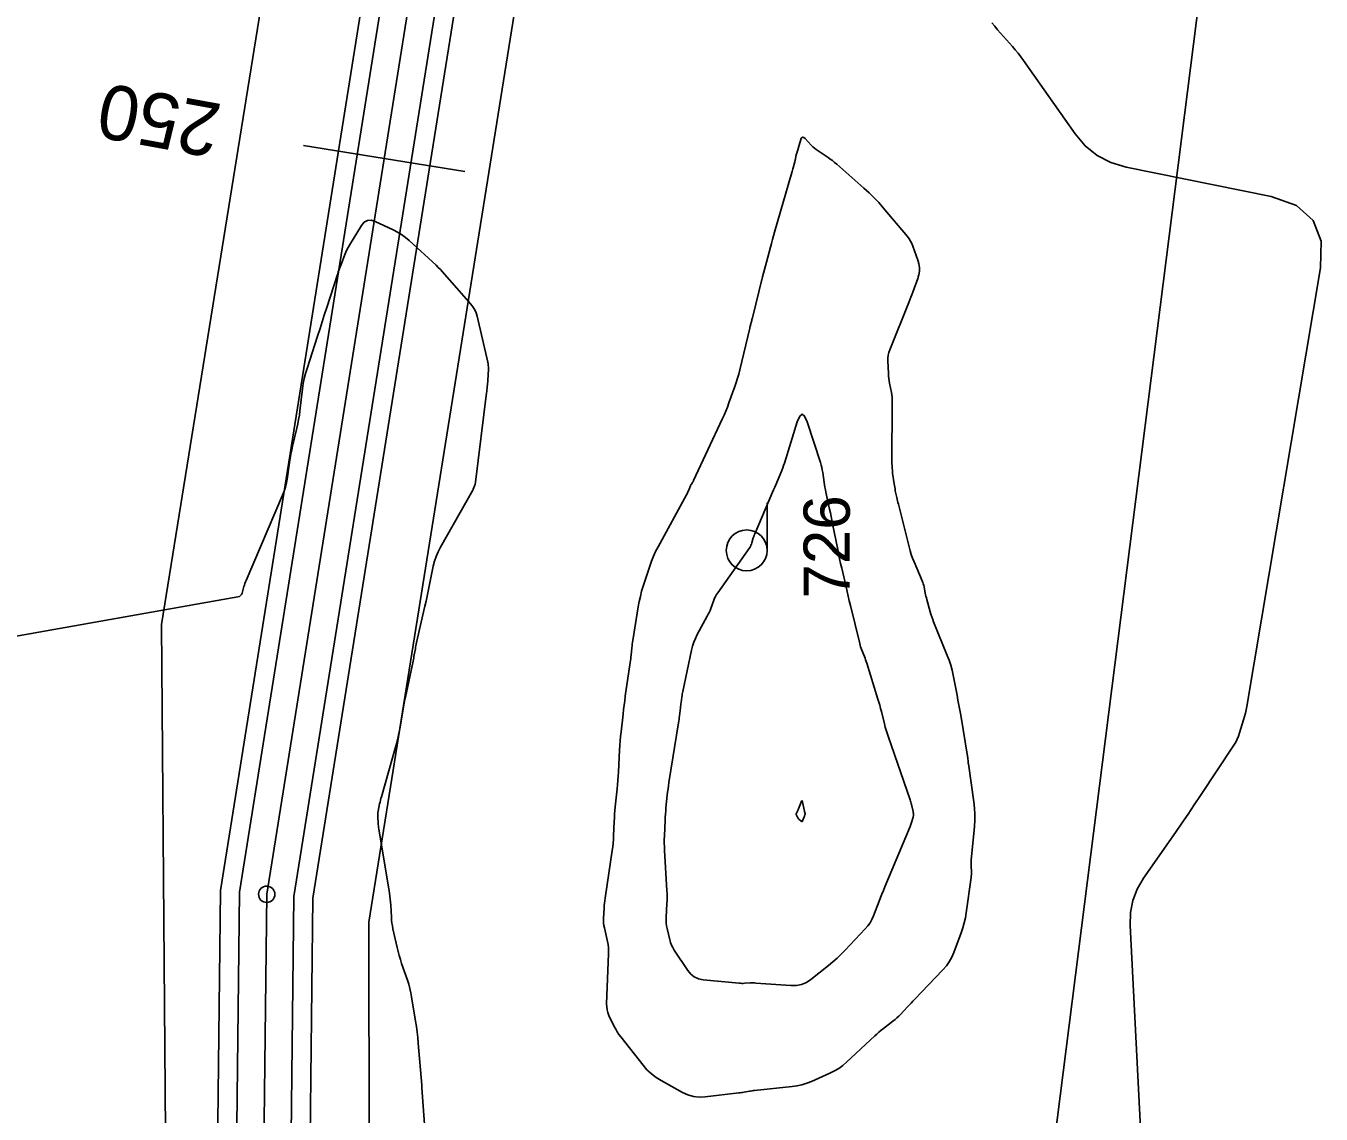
# Model space of a CAD drawing. Extents: x -534481 to -534262, y -1190577 to -1190138.
# Drawn here: x -534356 to -534332.21, y -1190332.35 to -1190312.37 of the extents above; entities that cross this region are included whole.
import ezdxf

# ---------------------------------------------------------------- set-up
doc = ezdxf.new("R2010")
doc.units = 0
for name, color, linetype in [('Bonity', 7, 'Continuous'), ('Definiční body', 7, 'Continuous'), ('Polygon budovy', 7, 'Continuous'), ('Vrstva 18', 7, 'Continuous'), ('Vrstva 19', 7, 'Continuous'), ('Vrstva 31', 7, 'Continuous'), ('Vrstva 32', 7, 'Continuous'), ('Vrstva 37', 7, 'Continuous'), ('Vrstva 48', 7, 'Continuous')]:
    doc.layers.add(name, color=color, linetype=linetype)

msp = doc.modelspace()

# ---------------------------------------------------------------- linework, layer by layer
at = {"layer": 'Bonity'}
msp.add_lwpolyline([(-534409.868, -1190391.439), (-534405.947, -1190382.816), (-534400.873, -1190377.487), (-534393.696, -1190372.718), (-534384.927, -1190365.477), (-534382.631, -1190361.148), (-534355.894, -1190347.823), (-534351.738, -1190342.389), (-534351.577, -1190328.316), (-534347.204, -1190300.921), (-534345.553, -1190283.64), (-534344.682, -1190264.494)], dxfattribs=at)
at = {"layer": 'Definiční body'}
msp.add_line((-534333.95, -1190307.91), (-534337.65, -1190337.15), dxfattribs=at)
for points in [[(-534353.4, -1190337.34), (-534353.51, -1190323.36), (-534348.1, -1190289.81), (-534348.02, -1190285.43)], [(-534346.16, -1190306.72), (-534349.7, -1190328.83), (-534349.69, -1190337.24)]]:
    msp.add_lwpolyline(points, dxfattribs=at)
at = {"layer": 'Vrstva 18'}
msp.add_lwpolyline([(-534334.528, -1190352.171), (-534335.719, -1190328.886), (-534335.712, -1190328.653), (-534335.669, -1190328.431), (-534335.588, -1190328.219), (-534335.471, -1190328.018), (-534334.888, -1190327.182), (-534334.771, -1190327.013), (-534334.655, -1190326.843), (-534334.54, -1190326.673), (-534334.426, -1190326.502), (-534333.813, -1190325.578), (-534333.78, -1190325.525), (-534333.751, -1190325.469), (-534333.727, -1190325.412), (-534333.707, -1190325.352), (-534333.634, -1190325.111), (-534333.616, -1190325.05), (-534333.601, -1190324.989), (-534333.588, -1190324.928), (-534333.576, -1190324.866), (-534332.224, -1190316.817), (-534332.211, -1190316.326), (-534332.357, -1190315.943), (-534332.662, -1190315.669), (-534333.126, -1190315.505), (-534335.793, -1190314.964), (-534336.073, -1190314.881), (-534336.322, -1190314.751), (-534336.542, -1190314.575), (-534336.73, -1190314.352), (-534337.677, -1190313.007), (-534337.725, -1190312.941), (-534337.775, -1190312.876), (-534337.827, -1190312.812), (-534337.88, -1190312.75), (-534338.098, -1190312.504), (-534338.152, -1190312.442), (-534338.205, -1190312.379), (-534338.257, -1190312.315)], dxfattribs=at)
msp.add_lwpolyline([(-534341.665, -1190329.934), (-534341.754, -1190329.972), (-534341.849, -1190329.991), (-534341.95, -1190329.993), (-534342.595, -1190329.945), (-534342.62, -1190329.944), (-534342.646, -1190329.943), (-534342.672, -1190329.943), (-534342.697, -1190329.944), (-534342.8, -1190329.95), (-534342.825, -1190329.951), (-534342.851, -1190329.951), (-534342.877, -1190329.95), (-534342.902, -1190329.948), (-534343.56, -1190329.884), (-534343.646, -1190329.867), (-534343.723, -1190329.832), (-534343.789, -1190329.781), (-534343.845, -1190329.713), (-534344.093, -1190329.339), (-534344.119, -1190329.295), (-534344.142, -1190329.248), (-534344.16, -1190329.2), (-534344.174, -1190329.15), (-534344.221, -1190328.946), (-534344.231, -1190328.895), (-534344.237, -1190328.844), (-534344.24, -1190328.792), (-534344.239, -1190328.74), (-534344.226, -1190328.487), (-534344.224, -1190328.427), (-534344.223, -1190328.368), (-534344.224, -1190328.308), (-534344.227, -1190328.249), (-534344.27, -1190327.513), (-534344.273, -1190327.446), (-534344.274, -1190327.379), (-534344.274, -1190327.312), (-534344.272, -1190327.245), (-534344.26, -1190326.961), (-534344.257, -1190326.903), (-534344.253, -1190326.845), (-534344.249, -1190326.786), (-534344.243, -1190326.728), (-534344.22, -1190326.496), (-534344.214, -1190326.438), (-534344.206, -1190326.38), (-534344.198, -1190326.322), (-534344.19, -1190326.264), (-534344.012, -1190325.168), (-534344.007, -1190325.136), (-534344.003, -1190325.103), (-534343.999, -1190325.071), (-534343.995, -1190325.039), (-534343.979, -1190324.895), (-534343.976, -1190324.87), (-534343.973, -1190324.845), (-534343.969, -1190324.819), (-534343.966, -1190324.794), (-534343.951, -1190324.694), (-534343.947, -1190324.669), (-534343.943, -1190324.644), (-534343.938, -1190324.619), (-534343.933, -1190324.594), (-534343.775, -1190323.835), (-534343.756, -1190323.76), (-534343.732, -1190323.688), (-534343.703, -1190323.617), (-534343.669, -1190323.548), (-534343.484, -1190323.211), (-534343.466, -1190323.176), (-534343.449, -1190323.14), (-534343.433, -1190323.104), (-534343.419, -1190323.067), (-534343.365, -1190322.919), (-534343.35, -1190322.882), (-534343.333, -1190322.847), (-534343.313, -1190322.813), (-534343.292, -1190322.78), (-534342.706, -1190321.948), (-534342.693, -1190321.928), (-534342.682, -1190321.907), (-534342.673, -1190321.886), (-534342.665, -1190321.864), (-534342.639, -1190321.773), (-534342.632, -1190321.75), (-534342.625, -1190321.728), (-534342.616, -1190321.706), (-534342.607, -1190321.684), (-534342.285, -1190320.933), (-534342.266, -1190320.889), (-534342.247, -1190320.844), (-534342.228, -1190320.8), (-534342.21, -1190320.756), (-534342.135, -1190320.579), (-534342.117, -1190320.534), (-534342.1, -1190320.489), (-534342.084, -1190320.444), (-534342.069, -1190320.398), (-534341.831, -1190319.643), (-534341.787, -1190319.538), (-534341.742, -1190319.502), (-534341.697, -1190319.537), (-534341.652, -1190319.642), (-534341.406, -1190320.39), (-534341.392, -1190320.435), (-534341.381, -1190320.479), (-534341.372, -1190320.524), (-534341.364, -1190320.57), (-534341.339, -1190320.753), (-534341.332, -1190320.799), (-534341.324, -1190320.844), (-534341.316, -1190320.89), (-534341.306, -1190320.935), (-534341.239, -1190321.245), (-534341.224, -1190321.311), (-534341.21, -1190321.378), (-534341.196, -1190321.445), (-534341.183, -1190321.512), (-534341.089, -1190321.983), (-534341.072, -1190322.07), (-534341.054, -1190322.156), (-534341.035, -1190322.242), (-534341.016, -1190322.329), (-534340.936, -1190322.673), (-534340.916, -1190322.758), (-534340.896, -1190322.844), (-534340.876, -1190322.93), (-534340.855, -1190323.016), (-534340.686, -1190323.71), (-534340.678, -1190323.741), (-534340.669, -1190323.772), (-534340.658, -1190323.802), (-534340.647, -1190323.832), (-534340.599, -1190323.952), (-534340.588, -1190323.982), (-534340.577, -1190324.013), (-534340.566, -1190324.043), (-534340.556, -1190324.074), (-534340.351, -1190324.732), (-534340.333, -1190324.788), (-534340.317, -1190324.845), (-534340.302, -1190324.902), (-534340.287, -1190324.959), (-534340.23, -1190325.188), (-534340.215, -1190325.245), (-534340.199, -1190325.302), (-534340.181, -1190325.358), (-534340.163, -1190325.414), (-534339.758, -1190326.582), (-534339.751, -1190326.604), (-534339.744, -1190326.626), (-534339.738, -1190326.648), (-534339.733, -1190326.67), (-534339.705, -1190326.794), (-534339.703, -1190326.804), (-534339.701, -1190326.814), (-534339.698, -1190326.834), (-534339.698, -1190326.839), (-534339.697, -1190326.845), (-534339.697, -1190326.85), (-534339.698, -1190326.855), (-534339.7, -1190326.876), (-534339.7, -1190326.881), (-534339.701, -1190326.887), (-534339.702, -1190326.892), (-534339.704, -1190326.897), (-534339.733, -1190326.999), (-534339.738, -1190327.018), (-534339.744, -1190327.036), (-534339.751, -1190327.054), (-534339.758, -1190327.072), (-534340.222, -1190328.178), (-534340.249, -1190328.244), (-534340.276, -1190328.311), (-534340.303, -1190328.377), (-534340.329, -1190328.444), (-534340.432, -1190328.711), (-534340.46, -1190328.776), (-534340.495, -1190328.837), (-534340.535, -1190328.895), (-534340.582, -1190328.948), (-534340.954, -1190329.341), (-534341.026, -1190329.415), (-534341.101, -1190329.486), (-534341.178, -1190329.555), (-534341.258, -1190329.621), (-534341.581, -1190329.879)], close=True, dxfattribs=at)
at = {"layer": 'Vrstva 19'}
for points in [[(-534343.631, -1190332.041), (-534343.736, -1190332.029), (-534343.839, -1190332), (-534343.938, -1190331.955), (-534344.331, -1190331.737), (-534344.425, -1190331.678), (-534344.512, -1190331.611), (-534344.593, -1190331.536), (-534344.665, -1190331.452), (-534345.074, -1190330.933), (-534345.108, -1190330.888), (-534345.138, -1190330.841), (-534345.167, -1190330.793), (-534345.192, -1190330.743), (-534345.29, -1190330.541), (-534345.31, -1190330.489), (-534345.325, -1190330.437), (-534345.332, -1190330.383), (-534345.334, -1190330.327), (-534345.296, -1190329.412), (-534345.296, -1190329.354), (-534345.299, -1190329.297), (-534345.306, -1190329.24), (-534345.317, -1190329.183), (-534345.375, -1190328.934), (-534345.384, -1190328.889), (-534345.389, -1190328.844), (-534345.391, -1190328.799), (-534345.391, -1190328.753), (-534345.381, -1190328.57), (-534345.378, -1190328.524), (-534345.374, -1190328.478), (-534345.369, -1190328.433), (-534345.363, -1190328.387), (-534345.23, -1190327.509), (-534345.221, -1190327.443), (-534345.214, -1190327.377), (-534345.208, -1190327.311), (-534345.205, -1190327.244), (-534345.194, -1190326.978), (-534345.19, -1190326.911), (-534345.186, -1190326.845), (-534345.181, -1190326.778), (-534345.175, -1190326.712), (-534345.141, -1190326.381), (-534345.134, -1190326.304), (-534345.127, -1190326.227), (-534345.122, -1190326.149), (-534345.117, -1190326.072), (-534345.096, -1190325.664), (-534345.091, -1190325.582), (-534345.085, -1190325.5), (-534345.078, -1190325.418), (-534345.069, -1190325.336), (-534345.032, -1190325.008), (-534345.023, -1190324.926), (-534345.013, -1190324.845), (-534345.002, -1190324.763), (-534344.99, -1190324.681), (-534344.9, -1190324.058), (-534344.895, -1190324.025), (-534344.891, -1190323.991), (-534344.887, -1190323.958), (-534344.884, -1190323.925), (-534344.871, -1190323.79), (-534344.867, -1190323.757), (-534344.863, -1190323.724), (-534344.858, -1190323.69), (-534344.853, -1190323.657), (-534344.753, -1190323.036), (-534344.735, -1190322.941), (-534344.714, -1190322.846), (-534344.69, -1190322.753), (-534344.662, -1190322.66), (-534344.542, -1190322.29), (-534344.51, -1190322.199), (-534344.474, -1190322.109), (-534344.433, -1190322.021), (-534344.388, -1190321.935), (-534343.866, -1190320.983), (-534343.857, -1190320.965), (-534343.848, -1190320.947), (-534343.84, -1190320.929), (-534343.832, -1190320.911), (-534343.795, -1190320.817), (-534343.792, -1190320.808), (-534343.787, -1190320.8), (-534343.783, -1190320.792), (-534343.777, -1190320.784), (-534343.754, -1190320.754), (-534343.749, -1190320.746), (-534343.744, -1190320.738), (-534343.739, -1190320.73), (-534343.735, -1190320.722), (-534343.209, -1190319.591), (-534343.176, -1190319.518), (-534343.145, -1190319.444), (-534343.115, -1190319.37), (-534343.087, -1190319.295), (-534342.978, -1190318.995), (-534342.952, -1190318.919), (-534342.928, -1190318.843), (-534342.907, -1190318.766), (-534342.887, -1190318.689), (-534342.706, -1190317.92), (-534342.702, -1190317.905), (-534342.698, -1190317.889), (-534342.694, -1190317.874), (-534342.69, -1190317.858), (-534342.673, -1190317.797), (-534342.669, -1190317.781), (-534342.665, -1190317.766), (-534342.661, -1190317.751), (-534342.657, -1190317.735), (-534342.468, -1190316.982), (-534342.45, -1190316.913), (-534342.433, -1190316.845), (-534342.415, -1190316.776), (-534342.397, -1190316.708), (-534342.326, -1190316.434), (-534342.308, -1190316.366), (-534342.29, -1190316.297), (-534342.271, -1190316.229), (-534342.251, -1190316.161), (-534341.933, -1190315.065), (-534341.926, -1190315.043), (-534341.92, -1190315.021), (-534341.914, -1190314.999), (-534341.908, -1190314.977), (-534341.879, -1190314.871), (-534341.875, -1190314.858), (-534341.872, -1190314.844), (-534341.869, -1190314.831), (-534341.866, -1190314.818), (-534341.856, -1190314.764), (-534341.853, -1190314.75), (-534341.85, -1190314.737), (-534341.846, -1190314.724), (-534341.843, -1190314.711), (-534341.767, -1190314.461), (-534341.753, -1190314.43), (-534341.735, -1190314.417), (-534341.713, -1190314.421), (-534341.687, -1190314.442), (-534341.575, -1190314.561), (-534341.546, -1190314.59), (-534341.516, -1190314.617), (-534341.484, -1190314.642), (-534341.451, -1190314.666), (-534341.267, -1190314.789), (-534341.226, -1190314.817), (-534341.185, -1190314.847), (-534341.146, -1190314.879), (-534341.107, -1190314.911), (-534340.608, -1190315.35), (-534340.514, -1190315.436), (-534340.424, -1190315.525), (-534340.337, -1190315.618), (-534340.253, -1190315.714), (-534339.809, -1190316.242), (-534339.778, -1190316.282), (-534339.751, -1190316.325), (-534339.728, -1190316.37), (-534339.709, -1190316.417), (-534339.618, -1190316.675), (-534339.613, -1190316.692), (-534339.608, -1190316.708), (-534339.604, -1190316.725), (-534339.601, -1190316.742), (-534339.589, -1190316.811), (-534339.587, -1190316.828), (-534339.586, -1190316.844), (-534339.587, -1190316.861), (-534339.59, -1190316.878), (-534339.602, -1190316.946), (-534339.605, -1190316.963), (-534339.609, -1190316.98), (-534339.614, -1190316.996), (-534339.619, -1190317.012), (-534339.709, -1190317.262), (-534339.726, -1190317.309), (-534339.744, -1190317.356), (-534339.762, -1190317.403), (-534339.781, -1190317.449), (-534340.131, -1190318.317), (-534340.149, -1190318.367), (-534340.16, -1190318.418), (-534340.167, -1190318.47), (-534340.167, -1190318.523), (-534340.158, -1190318.757), (-534340.155, -1190318.801), (-534340.151, -1190318.844), (-534340.145, -1190318.887), (-534340.137, -1190318.931), (-534340.104, -1190319.103), (-534340.097, -1190319.146), (-534340.091, -1190319.189), (-534340.088, -1190319.233), (-534340.088, -1190319.276), (-534340.093, -1190320.406), (-534340.092, -1190320.45), (-534340.09, -1190320.494), (-534340.086, -1190320.538), (-534340.081, -1190320.582), (-534340.053, -1190320.782), (-534340.048, -1190320.813), (-534340.043, -1190320.844), (-534340.037, -1190320.875), (-534340.031, -1190320.906), (-534340.004, -1190321.03), (-534339.997, -1190321.061), (-534339.99, -1190321.092), (-534339.983, -1190321.122), (-534339.975, -1190321.153), (-534339.778, -1190321.939), (-534339.759, -1190322.01), (-534339.738, -1190322.079), (-534339.713, -1190322.147), (-534339.686, -1190322.215), (-534339.538, -1190322.563), (-534339.527, -1190322.59), (-534339.518, -1190322.617), (-534339.51, -1190322.645), (-534339.504, -1190322.674), (-534339.481, -1190322.788), (-534339.475, -1190322.816), (-534339.468, -1190322.844), (-534339.461, -1190322.872), (-534339.454, -1190322.901), (-534339.39, -1190323.129), (-534339.376, -1190323.176), (-534339.361, -1190323.223), (-534339.344, -1190323.269), (-534339.327, -1190323.315), (-534339.076, -1190323.932), (-534339.043, -1190324.02), (-534339.014, -1190324.109), (-534338.989, -1190324.199), (-534338.969, -1190324.291), (-534338.897, -1190324.66), (-534338.88, -1190324.752), (-534338.863, -1190324.845), (-534338.846, -1190324.937), (-534338.83, -1190325.03), (-534338.705, -1190325.779), (-534338.703, -1190325.791), (-534338.701, -1190325.802), (-534338.7, -1190325.814), (-534338.699, -1190325.825), (-534338.695, -1190325.872), (-534338.694, -1190325.883), (-534338.692, -1190325.895), (-534338.691, -1190325.906), (-534338.689, -1190325.918), (-534338.587, -1190326.621), (-534338.574, -1190326.733), (-534338.568, -1190326.845), (-534338.569, -1190326.957), (-534338.576, -1190327.07), (-534338.638, -1190327.692), (-534338.64, -1190327.718), (-534338.641, -1190327.745), (-534338.641, -1190327.771), (-534338.64, -1190327.797), (-534338.635, -1190327.903), (-534338.634, -1190327.929), (-534338.635, -1190327.955), (-534338.636, -1190327.982), (-534338.639, -1190328.008), (-534338.729, -1190328.654), (-534338.745, -1190328.749), (-534338.765, -1190328.842), (-534338.791, -1190328.934), (-534338.822, -1190329.024), (-534338.957, -1190329.384), (-534338.994, -1190329.471), (-534339.04, -1190329.554), (-534339.094, -1190329.631), (-534339.156, -1190329.703), (-534339.678, -1190330.247), (-534339.711, -1190330.281), (-534339.743, -1190330.315), (-534339.775, -1190330.349), (-534339.807, -1190330.383), (-534339.935, -1190330.52), (-534339.968, -1190330.553), (-534340.002, -1190330.585), (-534340.037, -1190330.616), (-534340.074, -1190330.645), (-534340.25, -1190330.78), (-534340.291, -1190330.813), (-534340.332, -1190330.846), (-534340.371, -1190330.881), (-534340.41, -1190330.916), (-534340.926, -1190331.398), (-534340.996, -1190331.459), (-534341.071, -1190331.512), (-534341.15, -1190331.56), (-534341.233, -1190331.601), (-534341.573, -1190331.751), (-534341.659, -1190331.785), (-534341.747, -1190331.812), (-534341.837, -1190331.833), (-534341.928, -1190331.846), (-534342.616, -1190331.919), (-534342.64, -1190331.921), (-534342.664, -1190331.925), (-534342.688, -1190331.928), (-534342.712, -1190331.932), (-534342.808, -1190331.949), (-534342.832, -1190331.953), (-534342.856, -1190331.956), (-534342.88, -1190331.96), (-534342.904, -1190331.963), (-534343.521, -1190332.037)], [(-534341.739, -1190326.977), (-534341.746, -1190326.981), (-534341.753, -1190326.98), (-534341.762, -1190326.974), (-534341.804, -1190326.936), (-534341.811, -1190326.928), (-534341.818, -1190326.92), (-534341.824, -1190326.911), (-534341.829, -1190326.902), (-534341.849, -1190326.863), (-534341.853, -1190326.854), (-534341.854, -1190326.845), (-534341.852, -1190326.835), (-534341.848, -1190326.826), (-534341.828, -1190326.789), (-534341.823, -1190326.779), (-534341.818, -1190326.77), (-534341.814, -1190326.76), (-534341.81, -1190326.75), (-534341.762, -1190326.622), (-534341.753, -1190326.604), (-534341.745, -1190326.598), (-534341.739, -1190326.605), (-534341.733, -1190326.625), (-534341.702, -1190326.79), (-534341.699, -1190326.801), (-534341.696, -1190326.812), (-534341.69, -1190326.834), (-534341.689, -1190326.839), (-534341.689, -1190326.844), (-534341.689, -1190326.849), (-534341.691, -1190326.854), (-534341.701, -1190326.879), (-534341.707, -1190326.894), (-534341.734, -1190326.967)]]:
    msp.add_lwpolyline(points, close=True, dxfattribs=at)
msp.add_lwpolyline([(-534348.67, -1190332.619), (-534348.725, -1190331.87), (-534348.726, -1190331.857), (-534348.727, -1190331.832), (-534348.727, -1190331.82), (-534348.792, -1190331.047), (-534348.801, -1190330.946), (-534348.813, -1190330.845), (-534348.826, -1190330.745), (-534348.842, -1190330.644), (-534348.916, -1190330.201), (-534348.931, -1190330.123), (-534348.948, -1190330.045), (-534348.969, -1190329.969), (-534348.993, -1190329.893), (-534349.098, -1190329.585), (-534349.122, -1190329.513), (-534349.143, -1190329.439), (-534349.163, -1190329.366), (-534349.181, -1190329.291), (-534349.257, -1190328.952), (-534349.268, -1190328.898), (-534349.276, -1190328.844), (-534349.283, -1190328.789), (-534349.287, -1190328.735), (-534349.298, -1190328.515), (-534349.302, -1190328.46), (-534349.307, -1190328.406), (-534349.314, -1190328.351), (-534349.322, -1190328.297), (-534349.518, -1190327.114), (-534349.522, -1190327.087), (-534349.526, -1190327.06), (-534349.528, -1190327.034), (-534349.53, -1190327.007), (-534349.538, -1190326.899), (-534349.538, -1190326.872), (-534349.537, -1190326.845), (-534349.535, -1190326.818), (-534349.53, -1190326.791), (-534349.502, -1190326.653), (-534349.495, -1190326.622), (-534349.487, -1190326.59), (-534349.479, -1190326.559), (-534349.471, -1190326.527), (-534349.199, -1190325.572), (-534349.18, -1190325.5), (-534349.163, -1190325.428), (-534349.147, -1190325.356), (-534349.134, -1190325.283), (-534349.084, -1190324.991), (-534349.071, -1190324.918), (-534349.058, -1190324.845), (-534349.044, -1190324.772), (-534349.029, -1190324.699), (-534348.888, -1190324.034), (-534348.883, -1190324.006), (-534348.877, -1190323.978), (-534348.872, -1190323.95), (-534348.866, -1190323.921), (-534348.846, -1190323.808), (-534348.841, -1190323.78), (-534348.836, -1190323.752), (-534348.83, -1190323.723), (-534348.823, -1190323.695), (-534348.67, -1190323.028), (-534348.649, -1190322.936), (-534348.629, -1190322.844), (-534348.61, -1190322.752), (-534348.591, -1190322.66), (-534348.517, -1190322.292), (-534348.495, -1190322.201), (-534348.466, -1190322.113), (-534348.43, -1190322.028), (-534348.387, -1190321.945), (-534347.792, -1190320.898), (-534347.789, -1190320.893), (-534347.787, -1190320.888), (-534347.784, -1190320.882), (-534347.782, -1190320.877), (-534347.772, -1190320.85), (-534347.766, -1190320.834), (-534347.75, -1190320.787), (-534347.747, -1190320.777), (-534347.744, -1190320.767), (-534347.742, -1190320.757), (-534347.741, -1190320.747), (-534347.538, -1190319.109), (-534347.535, -1190319.083), (-534347.532, -1190319.056), (-534347.529, -1190319.03), (-534347.526, -1190319.003), (-534347.517, -1190318.897), (-534347.515, -1190318.871), (-534347.513, -1190318.844), (-534347.512, -1190318.818), (-534347.51, -1190318.791), (-534347.505, -1190318.664), (-534347.505, -1190318.635), (-534347.507, -1190318.605), (-534347.511, -1190318.575), (-534347.517, -1190318.546), (-534347.714, -1190317.704), (-534347.732, -1190317.643), (-534347.757, -1190317.585), (-534347.789, -1190317.531), (-534347.829, -1190317.48), (-534348.085, -1190317.186), (-534348.309, -1190316.93), (-534348.346, -1190316.888), (-534348.385, -1190316.847), (-534348.425, -1190316.807), (-534348.467, -1190316.768), (-534348.959, -1190316.314), (-534349.027, -1190316.256), (-534349.099, -1190316.204), (-534349.175, -1190316.158), (-534349.254, -1190316.117), (-534349.586, -1190315.962), (-534349.66, -1190315.939), (-534349.727, -1190315.944), (-534349.784, -1190315.977), (-534349.834, -1190316.037), (-534350.056, -1190316.397), (-534350.081, -1190316.439), (-534350.103, -1190316.482), (-534350.124, -1190316.526), (-534350.142, -1190316.571), (-534350.212, -1190316.753), (-534350.229, -1190316.799), (-534350.246, -1190316.845), (-534350.262, -1190316.891), (-534350.277, -1190316.937), (-534350.473, -1190317.542), (-534350.52, -1190317.686), (-534350.597, -1190317.927), (-534350.644, -1190318.071), (-534350.836, -1190318.663), (-534350.863, -1190318.754), (-534350.886, -1190318.846), (-534350.904, -1190318.94), (-534350.917, -1190319.034), (-534350.966, -1190319.44), (-534350.977, -1190319.521), (-534350.99, -1190319.601), (-534351.005, -1190319.681), (-534351.023, -1190319.761), (-534351.1, -1190320.087), (-534351.117, -1190320.162), (-534351.132, -1190320.237), (-534351.145, -1190320.312), (-534351.157, -1190320.388), (-534351.202, -1190320.692), (-534351.216, -1190320.768), (-534351.234, -1190320.842), (-534351.257, -1190320.915), (-534351.285, -1190320.986), (-534351.955, -1190322.552), (-534351.966, -1190322.581), (-534351.977, -1190322.609), (-534351.987, -1190322.638), (-534351.996, -1190322.668), (-534352.029, -1190322.786), (-534352.041, -1190322.812), (-534352.057, -1190322.832), (-534352.079, -1190322.847), (-534352.107, -1190322.855), (-534363.252, -1190324.831)], dxfattribs=at)
at = {"layer": 'Vrstva 31'}
msp.add_lwpolyline([(-534347.939, -1190315.044), (-534350.902, -1190314.571)], dxfattribs=at)
at = {"layer": 'Vrstva 32'}
for points in [[(-534409.97, -1190389.61), (-534406.662, -1190382.333), (-534401.423, -1190376.832), (-534394.204, -1190372.034), (-534385.599, -1190364.929), (-534383.254, -1190360.509), (-534356.45, -1190347.15), (-534352.584, -1190342.096), (-534352.426, -1190328.244), (-534348.048, -1190300.813), (-534346.401, -1190283.581), (-534345.607, -1190266.12)], [(-534409.916, -1190390.337), (-534406.368, -1190382.532), (-534401.196, -1190377.102), (-534393.995, -1190372.316), (-534385.322, -1190365.155), (-534382.997, -1190360.772), (-534356.221, -1190347.427), (-534352.236, -1190342.217), (-534352.076, -1190328.274), (-534347.7, -1190300.857), (-534346.052, -1190283.605), (-534345.255, -1190266.096)], [(-534409.363, -1190391.537), (-534405.527, -1190383.099), (-534400.549, -1190377.873), (-534393.398, -1190373.12), (-534384.532, -1190365.799), (-534382.264, -1190361.524), (-534355.568, -1190348.219), (-534351.24, -1190342.56), (-534351.077, -1190328.359), (-534346.708, -1190300.984), (-534345.054, -1190283.675), (-534344.256, -1190266.142)], [(-534409.02, -1190391.627), (-534405.233, -1190383.298), (-534400.323, -1190378.142), (-534393.189, -1190373.401), (-534384.256, -1190366.025), (-534382.008, -1190361.787), (-534355.339, -1190348.496), (-534350.891, -1190342.681), (-534350.728, -1190328.388), (-534346.36, -1190301.028), (-534344.705, -1190283.7), (-534343.908, -1190266.201)]]:
    msp.add_lwpolyline(points, dxfattribs=at)
at = {"layer": 'Vrstva 37'}
msp.add_circle((-534351.577, -1190328.316), 0.15, dxfattribs=at)
msp.add_circle((-534351.577, -1190328.316), 0.15, dxfattribs=at)
msp.add_circle((-534351.577, -1190328.316), 0.15, dxfattribs=at)
msp.add_circle((-534351.577, -1190328.316), 0.15, dxfattribs=at)
msp.add_circle((-534351.577, -1190328.316), 0.15, dxfattribs=at)
msp.add_circle((-534351.577, -1190328.316), 0.15, dxfattribs=at)
at = {"layer": 'Vrstva 48'}
msp.add_line((-534342.386, -1190322.002), (-534342.386, -1190321.127), dxfattribs=at)
msp.add_circle((-534342.761, -1190322.002), 0.375, dxfattribs=at)

# ---------------------------------------------------------------- texts
at = {"layer": 'Polygon budovy'}
msp.add_text('726', height=0.85, rotation=90, dxfattribs=at).set_placement((-534340.867, -1190322.887))
at = {"layer": 'Vrstva 31'}
msp.add_text('250', height=1, rotation=169.7045, dxfattribs=at).set_placement((-534352.37, -1190313.816))

doc.saveas('drawing.dxf')
